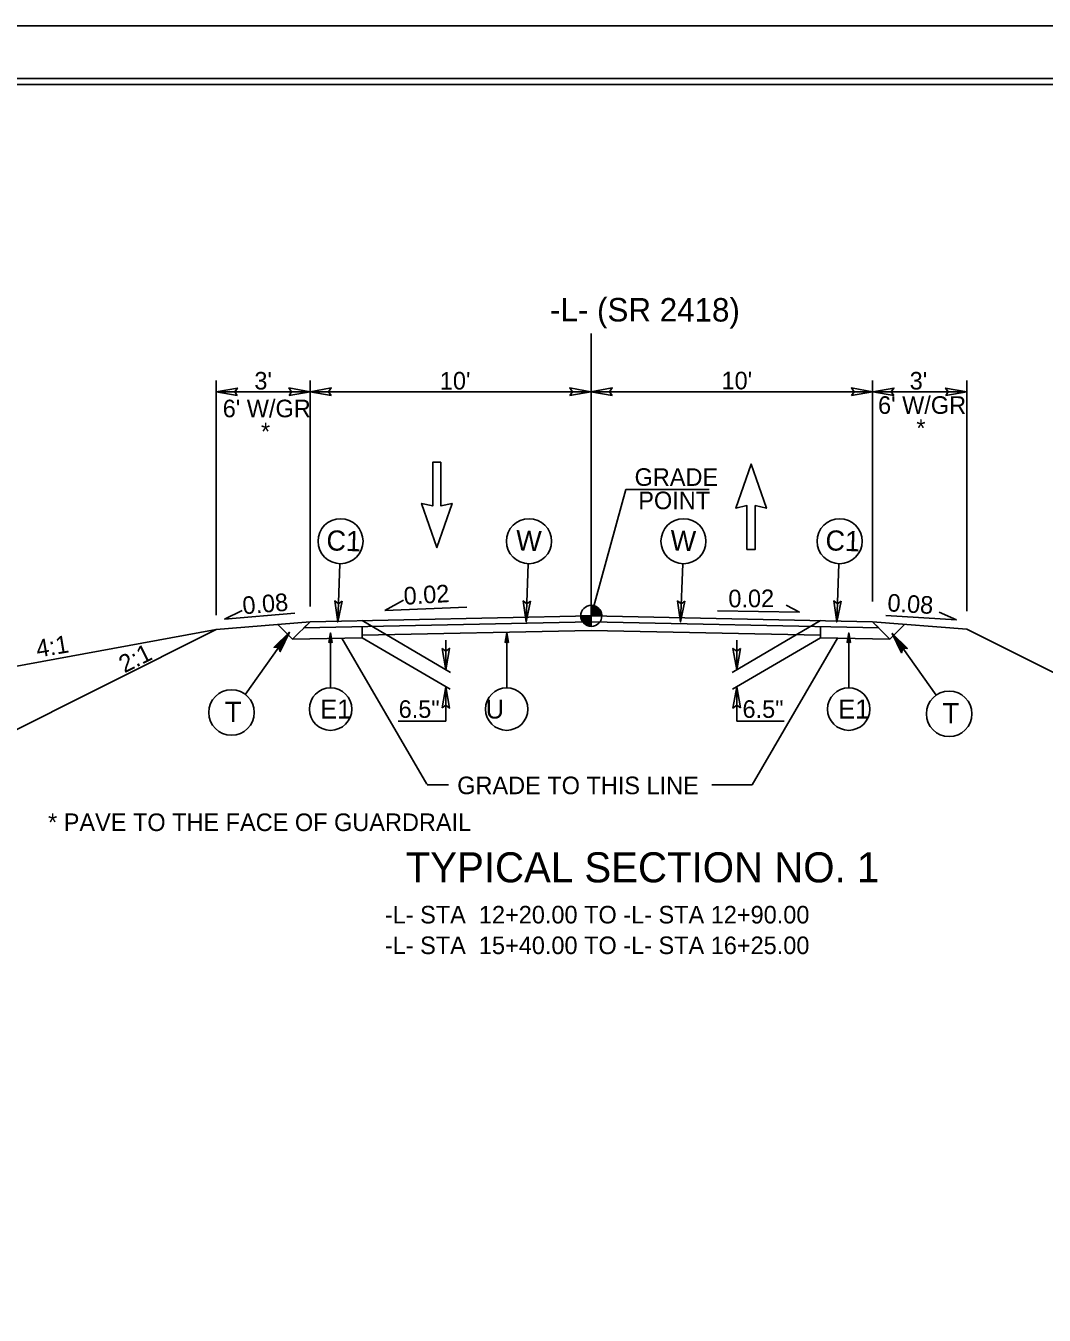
# Model space of a CAD drawing. Extents: x 1542177 to 1542464, y 45134 to 45344.
# Drawn here: x 1542250.02 to 1542284.79, y 45284.62 to 45328.62 of the extents above; entities that cross this region are included whole.
import ezdxf

# ---------------------------------------------------------------- set-up
doc = ezdxf.new("R2010")
doc.units = 0
for name, color, linetype in [('Default', 7, 'Continuous'), ('Old_Level_1', 7, 'Continuous'), ('Old_Level_2', 7, 'Continuous'), ('Sheet Cutting Line CELL', 7, 'Continuous'), ('Sheet Plot Border Inside CELL', 7, 'Continuous'), ('Sheet Plot Border Outside CELL', 7, 'Continuous'), ('Sheet Typical CELL', 7, 'Continuous'), ('Typical Detail Wedge3 CELL', 7, 'Continuous'), ('Typical ID Circle CELL', 7, 'Continuous'), ('Typical Terminator CELL', 7, 'Continuous'), ('Typical Text ID Circle CELL', 7, 'Continuous')]:
    doc.layers.add(name, color=color, linetype=linetype)

# ---------------------------------------------------------------- blocks, each defined once
blk = doc.blocks.new('GP')
at = {"layer": 'Default'}
blk.add_line((-0.001, -0.343), (0, 0), dxfattribs=at)
for points in [[(-0.343, 0), (0, 0), (-0.001, -0.343), (0, -0.343)], [(-0.343, 0), (-0.343, 0)], [(-0.341, 0), (-0.341, -0.037)], [(-0.335, 0), (-0.335, -0.078)], [(-0.328, 0), (-0.328, -0.102)], [(-0.321, 0), (-0.321, -0.123)], [(-0.314, 0), (-0.314, -0.139)], [(-0.307, 0), (-0.307, -0.153)], [(-0.3, 0), (-0.3, -0.166)], [(-0.293, 0), (-0.293, -0.178)], [(-0.286, 0), (-0.286, -0.189)], [(-0.28, 0), (-0.28, -0.199)], [(-0.273, 0), (-0.273, -0.208)], [(-0.266, 0), (-0.266, -0.216)], [(-0.259, 0), (-0.259, -0.225)], [(-0.252, 0), (-0.252, -0.232)], [(-0.245, 0), (-0.245, -0.24)], [(-0.238, 0), (-0.238, -0.247)], [(-0.232, 0), (-0.232, -0.253)], [(-0.225, 0), (-0.225, -0.259)], [(-0.218, 0), (-0.218, -0.265)], [(-0.211, 0), (-0.211, -0.271)], [(-0.204, 0), (-0.204, -0.276)], [(-0.197, 0), (-0.197, -0.281)], [(-0.191, 0), (-0.191, -0.285)], [(-0.184, 0), (-0.184, -0.29)], [(-0.177, 0), (-0.177, -0.294)], [(-0.17, 0), (-0.17, -0.298)], [(-0.163, 0), (-0.163, -0.302)], [(-0.156, 0), (-0.156, -0.306)], [(-0.149, 0), (-0.149, -0.309)], [(-0.142, 0), (-0.142, -0.312)], [(-0.135, 0), (-0.135, -0.315)], [(-0.129, 0), (-0.129, -0.318)], [(-0.122, 0), (-0.122, -0.321)], [(-0.115, 0), (-0.115, -0.323)], [(-0.108, 0), (-0.108, -0.325)], [(-0.101, 0), (-0.101, -0.328)], [(-0.095, 0), (-0.095, -0.329)], [(-0.088, 0), (-0.088, -0.331)], [(-0.081, 0), (-0.081, -0.333)], [(-0.074, 0), (-0.074, -0.335)], [(-0.067, 0), (-0.067, -0.336)], [(-0.06, 0), (-0.06, -0.338)], [(-0.053, 0), (-0.053, -0.338)], [(-0.046, 0), (-0.046, -0.34)], [(-0.04, 0), (-0.04, -0.341)], [(-0.033, 0), (-0.033, -0.341)], [(-0.026, 0), (-0.026, -0.342)], [(-0.019, 0), (-0.019, -0.342)], [(-0.012, 0), (-0.012, -0.343)], [(-0.005, 0), (-0.005, -0.343), (-0.005, -0.343)], [(0.343, 0), (0.343, 0), (0, 0), (0, 0.343), (0, 0.343)], [(0.003, 0.343), (0.003, 0.343), (0.003, 0)], [(0.01, 0.343), (0.01, 0)], [(0.017, 0.342), (0.017, 0)], [(0.024, 0.342), (0.024, 0)], [(0.03, 0.341), (0.03, 0)], [(0.037, 0.341), (0.037, 0)], [(0.044, 0.34), (0.044, 0)], [(0.051, 0.339), (0.051, 0)], [(0.058, 0.338), (0.058, 0)], [(0.065, 0.337), (0.065, 0)], [(0.072, 0.335), (0.072, 0)], [(0.079, 0.334), (0.079, 0)], [(0.085, 0.332), (0.085, 0)], [(0.092, 0.33), (0.092, 0)], [(0.099, 0.328), (0.099, 0)], [(0.106, 0.326), (0.106, 0)], [(0.113, 0.324), (0.113, 0)], [(0.12, 0.321), (0.12, 0)], [(0.126, 0.319), (0.126, 0)], [(0.133, 0.316), (0.133, 0)], [(0.14, 0.312), (0.14, 0)], [(0.147, 0.309), (0.147, 0)], [(0.154, 0.306), (0.154, 0)], [(0.161, 0.302), (0.161, 0)], [(0.168, 0.299), (0.168, 0)], [(0.175, 0.295), (0.175, 0)], [(0.181, 0.291), (0.181, 0)], [(0.188, 0.286), (0.188, 0)], [(0.195, 0.282), (0.195, 0)], [(0.202, 0.277), (0.202, 0)], [(0.209, 0.272), (0.209, 0)], [(0.216, 0.267), (0.216, 0)], [(0.223, 0.261), (0.223, 0)], [(0.229, 0.255), (0.229, 0)], [(0.236, 0.248), (0.236, 0)], [(0.243, 0.241), (0.243, 0)], [(0.25, 0.235), (0.25, 0)], [(0.257, 0.227), (0.257, 0)], [(0.264, 0.219), (0.264, 0)], [(0.271, 0.21), (0.271, 0)], [(0.277, 0.201), (0.277, 0)], [(0.284, 0.191), (0.284, 0)], [(0.291, 0.18), (0.291, 0)], [(0.298, 0.169), (0.298, 0)], [(0.305, 0.157), (0.305, 0)], [(0.312, 0.142), (0.312, 0)], [(0.319, 0.126), (0.319, 0)], [(0.326, 0.107), (0.326, 0)], [(0.332, 0.084), (0.332, 0)], [(0.339, 0.049), (0.339, 0)]]:
    blk.add_lwpolyline(points, dxfattribs=at)
blk.add_circle((0, 0), 0.343, dxfattribs=at)
for start, end in [(179.9905, 269.9905), (359.9905, 89.9905)]:
    blk.add_arc((0, 0), 0.343, start, end, dxfattribs=at)
blk = doc.blocks.new('ARROW3')
at = {"layer": 'Default'}
blk.add_lwpolyline([(-0.0267, -0.5547), (-0.0267, -0.2704), (-0.0991, -0.2874), (0, 0), (0.0991, -0.2874), (0.0267, -0.2704), (0.0267, -0.5547), (-0.0267, -0.5547)], dxfattribs=at)

msp = doc.modelspace()

# ---------------------------------------------------------------- linework, layer by layer
at = {"layer": 'Default'}
for p, q in [((1542269.328, 45308.481), (1542269.328, 45318.116)), ((1542256.523, 45308.502), (1542256.523, 45316.516)), ((1542259.729, 45308.801), (1542259.729, 45316.516)), ((1542278.929, 45308.965), (1542278.929, 45316.516)), ((1542282.148, 45308.646), (1542282.148, 45316.516)), ((1542256.523, 45316.127), (1542259.729, 45316.127)), ((1542259.729, 45316.127), (1542269.328, 45316.127)), ((1542269.328, 45316.127), (1542278.928, 45316.127)), ((1542278.928, 45316.127), (1542282.148, 45316.127)), ((1542269.329, 45308.481), (1542270.513, 45312.79)), ((1542270.513, 45312.79), (1542273.358, 45312.79)), ((1542262.279, 45308.663), (1542262.919, 45309.016)), ((1542256.804, 45308.37), (1542257.414, 45308.658)), ((1542259.204, 45308.57), (1542256.804, 45308.37)), ((1542262.279, 45308.663), (1542265.077, 45308.774)), ((1542273.634, 45308.651), (1542276.434, 45308.607)), ((1542276.434, 45308.607), (1542275.984, 45308.841)), ((1542281.792, 45308.344), (1542281.21, 45308.612)), ((1542256.523, 45308.01), (1542259.729, 45308.281)), ((1542259.133, 45307.686), (1542258.631, 45308.188)), ((1542259.729, 45308.281), (1542259.133, 45307.686)), ((1542259.506, 45308.058), (1542259.729, 45308.281)), ((1542259.506, 45308.058), (1542259.729, 45308.281)), ((1542269.324, 45308.273), (1542259.516, 45308.068)), ((1542259.729, 45308.281), (1542269.329, 45308.481)), ((1542269.324, 45308.273), (1542279.141, 45308.069)), ((1542269.328, 45308.481), (1542278.929, 45308.281)), ((1542279.524, 45307.686), (1542278.928, 45308.281)), ((1542278.928, 45308.281), (1542282.148, 45308.025)), ((1542279.388, 45308.488), (1542281.792, 45308.344)), ((1542279.524, 45307.686), (1542280.032, 45308.193)), ((1542248.516, 45304.006), (1542256.523, 45308.01)), ((1542248.699, 45306.579), (1542256.523, 45308.01)), ((1542261.508, 45307.735), (1542259.133, 45307.686)), ((1542261.508, 45307.818), (1542261.508, 45308.11)), ((1542261.508, 45307.818), (1542269.328, 45307.981)), ((1542261.508, 45307.735), (1542261.508, 45307.818)), ((1542269.328, 45307.981), (1542277.149, 45307.818)), ((1542277.149, 45307.818), (1542277.149, 45308.11)), ((1542277.149, 45307.735), (1542277.149, 45307.818)), ((1542277.149, 45307.735), (1542279.524, 45307.686)), ((1542282.148, 45308.025), (1542290.155, 45304.022))]:
    msp.add_line(p, q, dxfattribs=at)
for points in [[(1542257.243, 45316.003), (1542256.523, 45316.127), (1542257.247, 45316.255), (1542257.155, 45316.127)], [(1542259.009, 45316.005), (1542259.729, 45316.129), (1542259.005, 45316.257), (1542259.097, 45316.129)], [(1542260.449, 45316.005), (1542259.729, 45316.129), (1542260.453, 45316.257), (1542260.361, 45316.129)], [(1542268.597, 45316.004), (1542269.317, 45316.128), (1542268.593, 45316.256), (1542268.685, 45316.128)], [(1542270.037, 45316.004), (1542269.317, 45316.128), (1542270.041, 45316.256), (1542269.949, 45316.128)], [(1542278.212, 45316.004), (1542278.932, 45316.128), (1542278.208, 45316.256), (1542278.3, 45316.128)], [(1542279.655, 45316.001), (1542278.935, 45316.125), (1542279.659, 45316.253), (1542279.567, 45316.125)], [(1542281.428, 45316.003), (1542282.148, 45316.127), (1542281.424, 45316.255), (1542281.516, 45316.127)], [(1542264.238, 45307.363), (1542264.362, 45306.643), (1542264.49, 45307.367), (1542264.362, 45307.275)], [(1542274.418, 45307.363), (1542274.294, 45306.643), (1542274.166, 45307.367), (1542274.294, 45307.275)], [(1542264.238, 45305.34), (1542264.362, 45306.06), (1542264.49, 45305.336), (1542264.362, 45305.428)], [(1542274.418, 45305.34), (1542274.294, 45306.06), (1542274.166, 45305.336), (1542274.294, 45305.428)]]:
    msp.add_lwpolyline(points, close=True, dxfattribs=at)
msp.add_lwpolyline([(1542278.928, 45308.281), (1542279.141, 45308.069)], dxfattribs=at)
at = {"layer": 'Old_Level_2'}
for p, q in [((1542263.724, 45302.715), (1542264.455, 45302.715)), ((1542273.44, 45302.715), (1542274.819, 45302.715))]:
    msp.add_line(p, q, dxfattribs=at)
for points in [[(1542260.812, 45307.721), (1542263.714, 45302.732)], [(1542277.732, 45307.723), (1542274.819, 45302.715)]]:
    msp.add_lwpolyline(points, dxfattribs=at)
at = {"layer": 'Sheet Cutting Line CELL'}
msp.add_line((1542360.727, 45328.616), (1542226.007, 45328.616), dxfattribs=at)
at = {"layer": 'Sheet Plot Border Inside CELL'}
msp.add_lwpolyline([(1542360.367, 45326.82), (1542227.047, 45326.82), (1542227.047, 45242.412), (1542360.367, 45242.412)], close=True, dxfattribs=at)
at = {"layer": 'Sheet Plot Border Outside CELL'}
for points in [[(1542360.727, 45328.616), (1542226.007, 45328.616), (1542226.007, 45240.616), (1542360.727, 45240.616)], [(1542360.727, 45328.615), (1542226.007, 45328.615), (1542226.007, 45240.616), (1542360.727, 45240.616)]]:
    msp.add_lwpolyline(points, close=True, dxfattribs=at)
at = {"layer": 'Sheet Typical CELL'}
msp.add_lwpolyline([(1542359.367, 45326.616), (1542239.367, 45326.616), (1542239.367, 45242.616), (1542359.367, 45242.616)], close=True, dxfattribs=at)
at = {"layer": 'Typical Detail Wedge3 CELL'}
for points in [[(1542258.709, 45307.262), (1542258.66, 45307.412), (1542258.5, 45307.41), (1542259.021, 45307.922), (1542258.546, 45307.411), (1542258.592, 45307.412), (1542259.021, 45307.922), (1542258.636, 45307.412), (1542258.66, 45307.412), (1542259.021, 45307.922), (1542258.672, 45307.37), (1542258.687, 45307.327), (1542259.021, 45307.922), (1542258.701, 45307.284), (1542258.709, 45307.262), (1542259.021, 45307.922)], [(1542260.372, 45307.576), (1542260.428, 45307.618), (1542260.486, 45307.576), (1542260.428, 45307.898), (1542260.47, 45307.588), (1542260.453, 45307.601), (1542260.428, 45307.898), (1542260.437, 45307.612), (1542260.428, 45307.618), (1542260.428, 45307.898), (1542260.413, 45307.606), (1542260.397, 45307.594), (1542260.428, 45307.898), (1542260.38, 45307.582), (1542260.372, 45307.576), (1542260.428, 45307.898)], [(1542266.384, 45307.576), (1542266.441, 45307.618), (1542266.498, 45307.576), (1542266.441, 45307.898), (1542266.482, 45307.588), (1542266.466, 45307.601), (1542266.441, 45307.898), (1542266.45, 45307.612), (1542266.441, 45307.618), (1542266.441, 45307.898), (1542266.425, 45307.606), (1542266.409, 45307.594), (1542266.441, 45307.898), (1542266.393, 45307.582), (1542266.384, 45307.576), (1542266.441, 45307.898)], [(1542278.059, 45307.576), (1542278.116, 45307.618), (1542278.173, 45307.576), (1542278.116, 45307.898), (1542278.157, 45307.588), (1542278.14, 45307.601), (1542278.116, 45307.898), (1542278.124, 45307.612), (1542278.116, 45307.618), (1542278.116, 45307.898), (1542278.1, 45307.606), (1542278.084, 45307.594), (1542278.116, 45307.898), (1542278.067, 45307.582), (1542278.059, 45307.576), (1542278.116, 45307.898)], [(1542279.914, 45307.223), (1542279.964, 45307.373), (1542280.123, 45307.371), (1542279.603, 45307.883), (1542280.078, 45307.371), (1542280.032, 45307.373), (1542279.603, 45307.883), (1542279.988, 45307.373), (1542279.964, 45307.373), (1542279.603, 45307.883), (1542279.951, 45307.331), (1542279.937, 45307.288), (1542279.603, 45307.883), (1542279.922, 45307.245), (1542279.914, 45307.223), (1542279.603, 45307.883)]]:
    msp.add_lwpolyline(points, dxfattribs=at)
at = {"layer": 'Typical ID Circle CELL'}
for p, q in [((1542260.741, 45310.259), (1542260.672, 45308.272)), ((1542267.176, 45310.259), (1542267.106, 45308.272)), ((1542272.448, 45310.259), (1542272.378, 45308.272)), ((1542277.779, 45310.259), (1542277.709, 45308.272)), ((1542264.518, 45306.551), (1542261.508, 45308.318)), ((1542274.139, 45306.551), (1542277.149, 45308.318)), ((1542260.428, 45306.024), (1542260.428, 45307.898)), ((1542264.505, 45305.976), (1542261.508, 45307.735)), ((1542266.441, 45306.024), (1542266.441, 45307.898)), ((1542274.151, 45305.976), (1542277.149, 45307.735)), ((1542278.116, 45306.024), (1542278.116, 45307.898)), ((1542257.527, 45305.81), (1542258.66, 45307.412)), ((1542264.362, 45306.643), (1542264.362, 45307.648)), ((1542274.294, 45306.643), (1542274.294, 45307.648)), ((1542281.097, 45305.771), (1542279.964, 45307.373)), ((1542264.362, 45304.882), (1542264.362, 45306.06)), ((1542274.294, 45304.882), (1542274.294, 45306.06)), ((1542262.739, 45304.882), (1542264.362, 45304.882)), ((1542275.918, 45304.882), (1542274.294, 45304.882))]:
    msp.add_line(p, q, dxfattribs=at)
for centre, radius in [((1542260.768, 45311.027), 0.769), ((1542267.202, 45311.027), 0.769), ((1542272.475, 45311.027), 0.769), ((1542277.806, 45311.027), 0.769), ((1542257.045, 45305.183), 0.778), ((1542260.428, 45305.299), 0.725), ((1542266.441, 45305.299), 0.725), ((1542278.116, 45305.299), 0.725), ((1542281.546, 45305.136), 0.778)]:
    msp.add_circle(centre, radius, dxfattribs=at)
at = {"layer": 'Typical Terminator CELL'}
for points in [[(1542260.82, 45308.979), (1542260.672, 45308.272), (1542260.57, 45308.992), (1542260.694, 45308.896)], [(1542267.254, 45308.979), (1542267.106, 45308.272), (1542267.005, 45308.992), (1542267.128, 45308.896)], [(1542272.526, 45308.979), (1542272.378, 45308.272), (1542272.277, 45308.992), (1542272.4, 45308.896)], [(1542277.857, 45308.979), (1542277.709, 45308.272), (1542277.608, 45308.992), (1542277.731, 45308.896)]]:
    msp.add_lwpolyline(points, close=True, dxfattribs=at)

# ---------------------------------------------------------------- block references
at = {"layer": 'Default', "xscale": 5.249333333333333, "yscale": 5.249333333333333, "rotation": 180}
msp.add_blockref('ARROW3', (1542264.056, 45310.81), dxfattribs=at)
at = {"layer": 'Default'}
for name, p, xscale, yscale in [('ARROW3', (1542274.784, 45313.661), 5.249333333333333, 5.249333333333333), ('GP', (1542269.329, 45308.481), 1.0498642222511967, 1.0498642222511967)]:
    msp.add_blockref(name, p, dxfattribs=dict(at, xscale=xscale, yscale=yscale))

# ---------------------------------------------------------------- texts
for s, height, rotation, p in [('-L- (SR 2418)', 0.8, 359.9469, (1542267.92, 45318.529)), ('0.02', 0.6, 3.4691, (1542262.94, 45308.858)), ('0.08', 0.6, 4.7617, (1542257.444, 45308.531)), ('0.08', 0.6, 356.5617, (1542279.425, 45308.636)), ('4:1', 0.6, 9.4622, (1542250.425, 45307.055)), ('2:1', 0.6, 26.5651, (1542253.391, 45306.518))]:
    msp.add_text(s, height=height, rotation=rotation, dxfattribs=at).set_placement(p)
for s, height, p in [("3'", 0.6, (1542257.826, 45316.204)), ("10'", 0.6, (1542264.158, 45316.204)), ("10'", 0.6, (1542273.774, 45316.21)), ("3'", 0.6, (1542280.198, 45316.204)), ("6' W/GR", 0.6, (1542256.745, 45315.257)), ("6' W/GR", 0.6, (1542279.118, 45315.374)), ('*', 0.6, (1542280.425, 45314.588)), ('*', 0.6, (1542258.053, 45314.47)), ('GRADE', 0.6, (1542270.806, 45312.916)), ('POINT', 0.6, (1542270.932, 45312.12)), ('* PAVE TO THE FACE OF GUARDRAIL', 0.6, (1542250.783, 45301.137)), ('TYPICAL SECTION NO. 1', 1.02627, (1542262.991, 45299.386)), ('-L- STA  12+20.00 TO -L- STA 12+90.00', 0.6, (1542262.281, 45297.984)), ('-L- STA  15+40.00 TO -L- STA 16+25.00', 0.6, (1542262.281, 45296.938))]:
    msp.add_text(s, height=height, dxfattribs=at).set_placement(p)
at = {"layer": 'Old_Level_1'}
msp.add_text('GRADE TO THIS LINE', height=0.6, dxfattribs=at).set_placement((1542264.751, 45302.395))
at = {"layer": 'Typical ID Circle CELL'}
msp.add_text('0.02', height=0.6, rotation=0.2853, dxfattribs=at).set_placement((1542274.01, 45308.771))
for p in [(1542262.751, 45305), (1542274.491, 45305)]:
    msp.add_text('6.5"', height=0.6, dxfattribs=at).set_placement(p)
at = {"layer": 'Typical Text ID Circle CELL'}
for s, height, rotation, p in [('C1', 0.6886, 358, (1542260.277, 45310.719)), ('W', 0.689, 358, (1542266.748, 45310.718)), ('W', 0.689, 358, (1542272.02, 45310.718)), ('C1', 0.6886, 358, (1542277.314, 45310.719)), ('E1', 0.649, 360, (1542260.073, 45304.976)), (' U ', 0.649, 360, (1542265.483, 45304.976)), (' U ', 0.649, 360, (1542265.483, 45304.976)), ('E1', 0.649, 360, (1542277.76, 45304.976))]:
    msp.add_text(s, height=height, rotation=rotation, dxfattribs=at).set_placement(p)
for p in [(1542256.817, 45304.855), (1542281.318, 45304.808)]:
    msp.add_text('T', height=0.696, dxfattribs=at).set_placement(p)

doc.saveas('drawing.dxf')
